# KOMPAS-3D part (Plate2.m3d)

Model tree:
1. Plane XY
2. Plane ZX
3. Plane ZY
4. X Axis
5. Y Axis
6. Z Axis
7. Origin
8. Sketch:1
9. Extrude:1
     Wall Thickness 1 = 1; Wall Thickness 2 = 1; Distance 1 = 20; Distance 2 = 10

Referenced files in D:\Documents and Settings\kashirsky\Рабочий стол\Seminar\: Cottage_balcony.a3d
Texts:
  Steel DIN 17102
  Three Point Plane
  Plane at Angle
  Line and Point Plane
  Axis through Two Vertices
  Axis of Feature
  Axis of Conical Surface
  Axis through Edge
  Trim by Surface
  Trim by Sketch
  Feature with No History
  Intersection Axis of Two Planes
  Two Line Plane
  Line and Face Plane
  Bend by line
  Hole in sheet body
  Cut in sheet body
  Point in CM
  Linear Dimension from Line to Point
  Surface Finish Symbol
  Geometric Tolerance Symbol
  Leader #1
  Leader #2
  Leader #3
  Shape Deviations and Datum
  Node point number
  Mark of coordination axis
  Node point designation
  Mark/Reference designation with leader
  Mark/reference designation on line
  Mark/Reference designation without leader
